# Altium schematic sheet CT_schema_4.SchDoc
size 282 x 169 mm
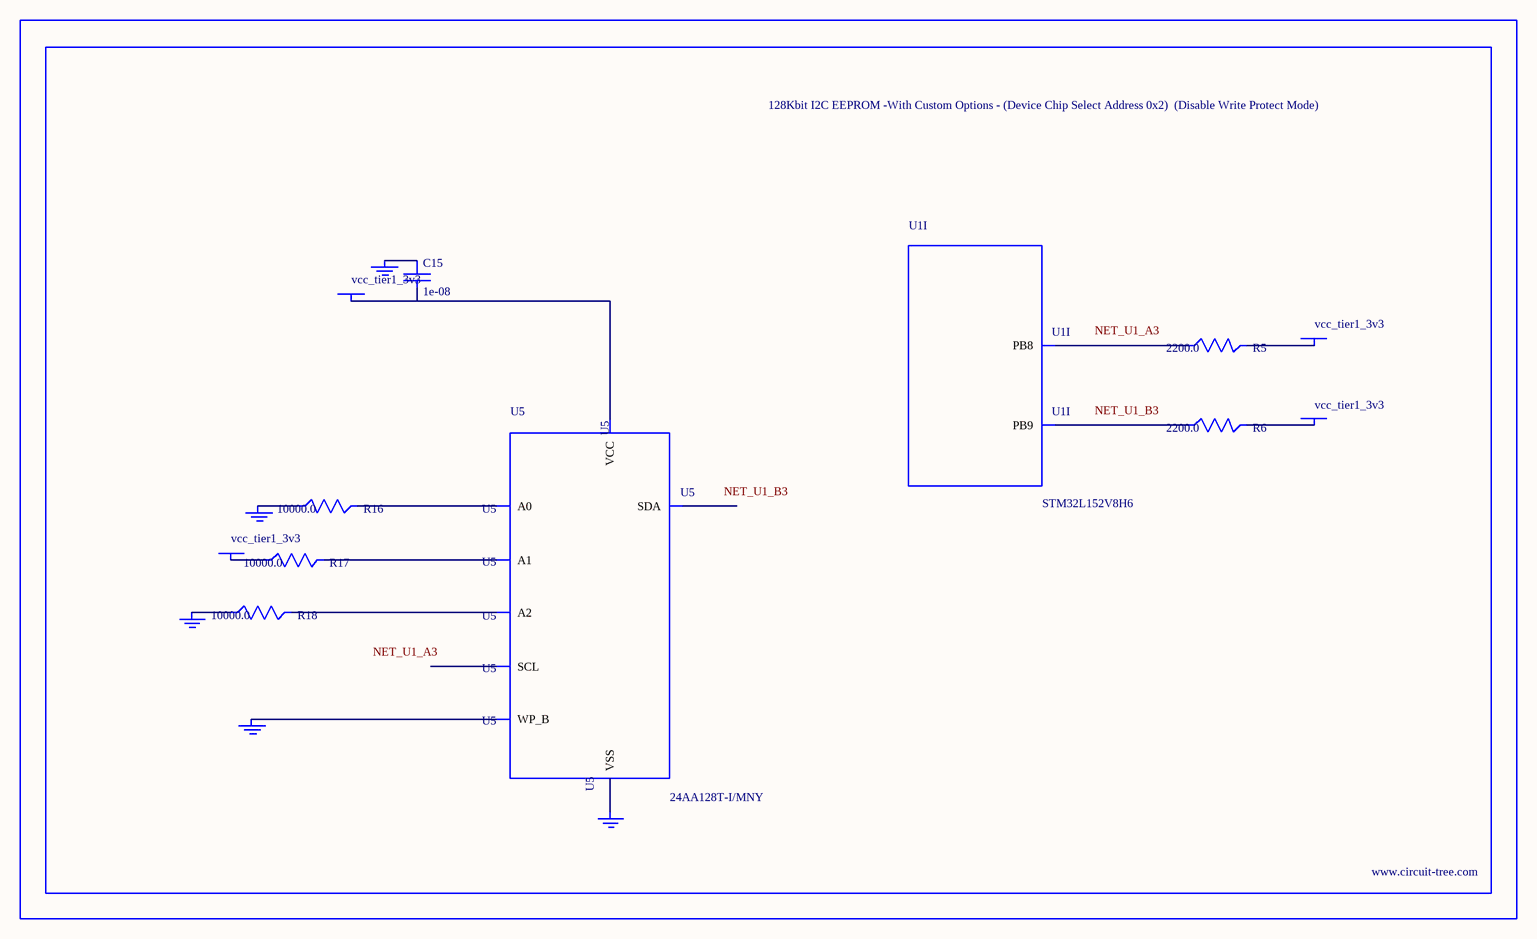
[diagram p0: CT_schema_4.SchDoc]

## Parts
BORDER3  (no value)
C15  1e-08  [C0402]
GND_INSTANCE_3_0  (no value)
GND_INSTANCE_3_1  (no value)
GND_INSTANCE_3_2  (no value)
GND_INSTANCE_3_3  (no value)
GND_INSTANCE_3_4  (no value)
POWER_INSTANCE_3_0  vcc_tier1_3v3
POWER_INSTANCE_3_1  vcc_tier1_3v3
POWER_INSTANCE_3_2  vcc_tier1_3v3
POWER_INSTANCE_3_3  vcc_tier1_3v3
R5  2200.0  [R0603]
R6  2200.0  [R0603]
R16  10000.0  [R0603]
R17  10000.0  [R0603]
R18  10000.0  [R0603]
U1  STM32L152V8H6  [UFBGA100]  (part I of 10)
U5  24AA128T-I/MNY  [TDFN-8/6MM]

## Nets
NetC15_1: C15.1 GND_INSTANCE_3_3.0(GND)
NetC15_2: C15.2 POWER_INSTANCE_3_1.0(PWR) U5.8(VCC)
NetGND_INSTANCE_3_0_0: GND_INSTANCE_3_0.0(GND) R16.1
NetGND_INSTANCE_3_1_0: GND_INSTANCE_3_1.0(GND) R18.1
NetGND_INSTANCE_3_2_0: GND_INSTANCE_3_2.0(GND) U5.7(WP_B)
NetGND_INSTANCE_3_4_0: GND_INSTANCE_3_4.0(GND) U5.4(VSS)
NetPOWER_INSTANCE_3_0_0: POWER_INSTANCE_3_0.0(PWR) R17.1
NetPOWER_INSTANCE_3_2_0: POWER_INSTANCE_3_2.0(PWR) R5.2
NetPOWER_INSTANCE_3_3_0: POWER_INSTANCE_3_3.0(PWR) R6.2
NetR5_1: R5.1 U1.A3(PB8)
NetR6_1: R6.1 U1.B3(PB9)
NetR16_2: R16.2 U5.1(A0)
NetR17_2: R17.2 U5.2(A1)
NetR18_2: R18.2 U5.3(A2)

Not connected (* = marked no-connect by the designer): U5 5(SDA) 6(SCL)

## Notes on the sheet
- Labels drawn without touching a wire or pin: NET_U1_A3, NET_U1_B3

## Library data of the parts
BORDER3 = BORDER_PAGE3
C15 = C0402C103K3RAC
GND_INSTANCE_3_0-GND_INSTANCE_3_4 = GND
POWER_INSTANCE_3_0-POWER_INSTANCE_3_3 = PWR
R5 R6 = RC0603JR-072K2L
R16-R18 = RC0603JR-0710KL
